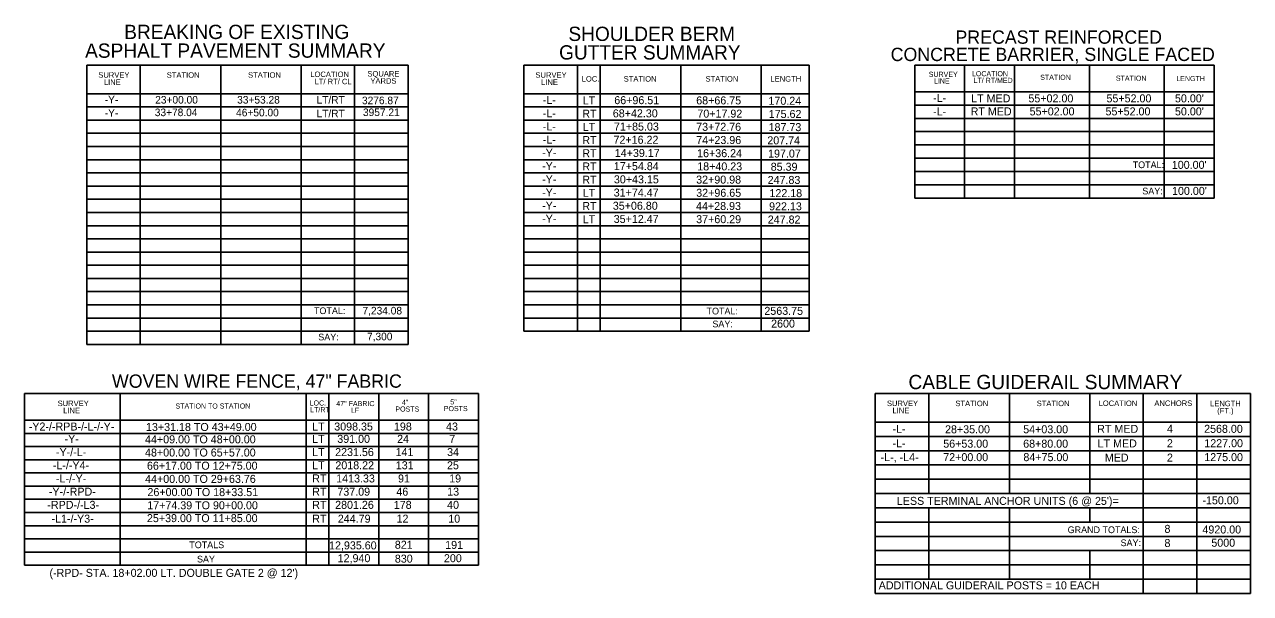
# Model space of a CAD drawing. Extents: x 573680 to 576464, y -53324 to -52224.
# Drawn here: x 575496 to 576464, y -53290 to -52840 of the extents above; entities that cross this region are included whole.
import ezdxf

# ---------------------------------------------------------------- set-up
doc = ezdxf.new("R2010")
doc.units = 0
for name, color, linetype in [('Old_Level_1', 7, 'Continuous'), ('Prop Dimension Text', 7, 'Continuous'), ('Sheet Summary Combination CELL', 7, 'Continuous'), ('Sheet Summary Combination Grid CELL', 7, 'Continuous')]:
    doc.layers.add(name, color=color, linetype=linetype)

msp = doc.modelspace()

# ---------------------------------------------------------------- linework, layer by layer
at = {"layer": 'Sheet Summary Combination CELL'}
for p, q in [((575672.56, -52872.26), (575672.56, -52872.26)), ((575678.2, -52872.35), (575678.2, -52872.35)), ((575686.37, -52872.17), (575686.37, -52872.17)), ((575691.42, -52872.26), (575691.42, -52872.26)), ((576017.76, -52872.26), (576017.76, -52872.26)), ((576023.4, -52872.35), (576023.4, -52872.35)), ((576031.57, -52872.17), (576031.57, -52872.17)), ((576036.62, -52872.26), (576036.62, -52872.26)), ((576317.64, -52872.25), (576317.64, -52872.25)), ((576322.89, -52872.34), (576322.89, -52872.34)), ((576330.49, -52872.17), (576330.49, -52872.17)), ((576335.2, -52872.25), (576335.2, -52872.25)), ((575697.34, -53131.65), (575697.34, -53131.65)), ((575702.59, -53131.73), (575702.59, -53131.73)), ((575710.2, -53131.56), (575710.2, -53131.56)), ((575714.9, -53131.65), (575714.9, -53131.65)), ((576295.3, -53131.65), (576295.3, -53131.65)), ((576300.94, -53131.74), (576300.94, -53131.74)), ((576309.1, -53131.56), (576309.1, -53131.56)), ((576314.16, -53131.65), (576314.16, -53131.65))]:
    msp.add_line(p, q, dxfattribs=at)
at = {"layer": 'Sheet Summary Combination Grid CELL'}
for p, q in [((575545.08, -52872.21), (575799, -52872.21)), ((575545.08, -52872.21), (575545.08, -53092.83)), ((575587.41, -52872.21), (575587.41, -53092.83)), ((575650.9, -52872.21), (575650.9, -53092.83)), ((575714.35, -52872.21), (575714.35, -53092.83)), ((575756.67, -52872.21), (575756.67, -53092.83)), ((575799, -52872.21), (575799, -53092.83)), ((575890.28, -52872.21), (576115.56, -52872.21)), ((575890.28, -52872.21), (575890.28, -53082.41)), ((575932.61, -52872.21), (575932.61, -53082.41)), ((575950.66, -52872.21), (575950.66, -53082.41)), ((576014.15, -52872.21), (576014.15, -53082.41)), ((576077.6, -52872.21), (576077.6, -53082.41)), ((576115.56, -52872.21), (576115.56, -53082.41)), ((576198.96, -52872.21), (576435.35, -52872.21)), ((576198.96, -52872.21), (576198.96, -52977.24)), ((576238.36, -52872.21), (576238.36, -52977.24)), ((576277.81, -52872.21), (576277.81, -52977.24)), ((576336.88, -52872.21), (576336.88, -52977.24)), ((576395.95, -52872.21), (576395.95, -52977.24)), ((576435.35, -52872.21), (576435.35, -52977.24)), ((575545.08, -52894.78), (575799, -52894.78)), ((575890.28, -52894.78), (576115.56, -52894.78)), ((576198.96, -52893.22), (576435.35, -52893.22)), ((575545.08, -52905.2), (575799, -52905.2)), ((575890.28, -52905.2), (576115.56, -52905.2)), ((576198.96, -52903.72), (576435.35, -52903.72)), ((575545.08, -52915.62), (575799, -52915.62)), ((575890.28, -52915.62), (576115.56, -52915.62)), ((576198.96, -52914.22), (576435.35, -52914.22)), ((576198.96, -52924.73), (576435.35, -52924.73)), ((575545.08, -52926.05), (575799, -52926.05)), ((575890.28, -52926.05), (576115.56, -52926.05)), ((576198.96, -52935.23), (576435.35, -52935.23)), ((575545.08, -52936.47), (575799, -52936.47)), ((575890.28, -52936.47), (576115.56, -52936.47)), ((575545.08, -52946.89), (575799, -52946.89)), ((575890.28, -52946.89), (576115.56, -52946.89)), ((576198.96, -52945.73), (576435.35, -52945.73)), ((576198.96, -52945.73), (576435.35, -52945.73)), ((576198.96, -52945.73), (576435.35, -52945.73)), ((575545.08, -52957.32), (575799, -52957.32)), ((575890.28, -52957.32), (576115.56, -52957.32)), ((576198.96, -52956.24), (576435.35, -52956.24)), ((575545.08, -52967.74), (575799, -52967.74)), ((575890.28, -52967.74), (576115.56, -52967.74)), ((576198.96, -52966.74), (576435.35, -52966.74)), ((575545.08, -52978.17), (575799, -52978.17)), ((575890.28, -52978.17), (576115.56, -52978.17)), ((576198.96, -52977.24), (576435.35, -52977.24)), ((575545.08, -52988.59), (575799, -52988.59)), ((575890.28, -52988.59), (576115.56, -52988.59)), ((575545.08, -52999.01), (575799, -52999.01)), ((575890.28, -52999.01), (576115.56, -52999.01)), ((575545.08, -53009.44), (575799, -53009.44)), ((575890.28, -53009.44), (576115.56, -53009.44)), ((575545.08, -53019.86), (575799, -53019.86)), ((575890.28, -53019.86), (576115.56, -53019.86)), ((575545.08, -53030.29), (575799, -53030.29)), ((575545.08, -53030.29), (575799, -53030.29)), ((575545.08, -53030.29), (575799, -53030.29)), ((575890.28, -53030.29), (576115.56, -53030.29)), ((575545.08, -53040.71), (575799, -53040.71)), ((575890.28, -53040.71), (576115.56, -53040.71)), ((575545.08, -53051.13), (575799, -53051.13)), ((575890.28, -53051.13), (576115.56, -53051.13)), ((575545.08, -53061.56), (575799, -53061.56)), ((575890.28, -53061.56), (576115.56, -53061.56)), ((575545.08, -53071.98), (575799, -53071.98)), ((575890.28, -53071.98), (576115.56, -53071.98)), ((575545.08, -53082.41), (575799, -53082.41)), ((575890.28, -53082.41), (576115.56, -53082.41)), ((575545.08, -53092.83), (575799, -53092.83)), ((575495.97, -53131.61), (575854.46, -53131.61)), ((575495.97, -53131.61), (575495.97, -53267.27)), ((575571.5, -53131.61), (575571.5, -53267.27)), ((575718.45, -53131.61), (575718.45, -53267.27)), ((575736.24, -53131.61), (575736.24, -53267.27)), ((575775.65, -53131.61), (575775.65, -53267.27)), ((575815.06, -53131.61), (575815.06, -53267.27)), ((575854.46, -53131.61), (575854.46, -53267.27)), ((576167.82, -53131.61), (576464.06, -53131.61)), ((576167.82, -53131.61), (576167.82, -53289.54)), ((576210.15, -53131.61), (576210.15, -53210.57)), ((576273.64, -53131.61), (576273.64, -53210.57)), ((576337.08, -53131.61), (576337.08, -53210.57)), ((576379.41, -53131.61), (576379.41, -53289.54)), ((576421.74, -53131.61), (576421.74, -53289.54)), ((576464.06, -53131.61), (576464.06, -53289.54)), ((575495.97, -53152.61), (575854.46, -53152.61)), ((576167.82, -53154.17), (576464.06, -53154.17)), ((575495.97, -53163.04), (575854.46, -53163.04)), ((576167.82, -53165.45), (576464.06, -53165.45)), ((575495.97, -53173.46), (575854.46, -53173.46)), ((576167.82, -53176.73), (576464.06, -53176.73)), ((575495.97, -53183.88), (575854.46, -53183.88)), ((575495.97, -53194.31), (575854.46, -53194.31)), ((576167.82, -53188.01), (576464.06, -53188.01)), ((575495.97, -53204.73), (575854.46, -53204.73)), ((576167.82, -53199.29), (576464.06, -53199.29)), ((575495.97, -53215.15), (575854.46, -53215.15)), ((576167.82, -53210.57), (576464.06, -53210.57)), ((576167.82, -53210.57), (576464.06, -53210.57)), ((575495.97, -53225.58), (575854.46, -53225.58)), ((575571.5, -53225.58), (575854.46, -53225.58)), ((575571.5, -53225.58), (575854.46, -53225.58)), ((576167.82, -53221.86), (576464.06, -53221.86)), ((576210.15, -53221.86), (576210.15, -53278.26)), ((576273.64, -53221.86), (576273.64, -53278.26)), ((576337.08, -53221.86), (576337.08, -53233.14)), ((576167.82, -53233.14), (576464.06, -53233.14)), ((575495.97, -53236.08), (575854.46, -53236.08)), ((575571.5, -53236), (575854.46, -53236)), ((575571.5, -53236), (575854.46, -53236)), ((576167.82, -53244.42), (576464.06, -53244.42)), ((575495.97, -53246.43), (575854.46, -53246.43)), ((575571.5, -53246.43), (575854.46, -53246.43)), ((575495.97, -53256.85), (575854.46, -53256.85)), ((575571.5, -53256.85), (575854.46, -53256.85)), ((576167.82, -53255.7), (576464.06, -53255.7)), ((576337.08, -53255.7), (576337.08, -53278.26)), ((575495.97, -53267.27), (575854.46, -53267.27)), ((575571.5, -53267.27), (575854.46, -53267.27)), ((576167.82, -53266.98), (576464.06, -53266.98)), ((576167.82, -53278.26), (576464.06, -53278.26)), ((576167.82, -53289.54), (576464.06, -53289.54))]:
    msp.add_line(p, q, dxfattribs=at)

# ---------------------------------------------------------------- texts
at = {"layer": 'Old_Level_1'}
for s, p in [('TOTALS', (575626.08, -53253.75)), ('SAY', (575632.17, -53265.04))]:
    msp.add_text(s, height=5.293, rotation=0.00004, dxfattribs=at).set_placement(p)
at = {"layer": 'Prop Dimension Text'}
for s, height, p in [('-Y-', 6, (575559.33, -52902.39)), ('23+00.00', 6, (575599.17, -52902.55)), ('33+53.28', 6, (575663.88, -52902.55)), ('LT/RT', 6, (575726.58, -52902.58)), ('-L-', 6.317, (576213.42, -52901.25)), ('LT MED', 6.317, (576243.49, -52901.6)), ('55+02.00', 6.317, (576288.71, -52901.6)), ('55+52.00', 6.317, (576350.34, -52901.6)), ("50.00'", 6.317, (576404.44, -52901.6)), ('3276.87', 6, (575762.45, -52903.06)), ('-L-', 6.317, (575905.19, -52902.89)), ('LT', 6.317, (575936.8, -52903.26)), ('66+96.51', 6.317, (575961.68, -52903.03)), ('68+66.75', 6.317, (576026.39, -52903.22)), ('170.24', 6.317, (576083.43, -52903.49)), ('-L-', 6.317, (576213.42, -52911.89)), ('RT MED', 6.317, (576243.11, -52911.89)), ('55+02.00', 6.317, (576289.65, -52911.89)), ('55+52.00', 6.317, (576349.58, -52911.89)), ("50.00'", 6.317, (576404.44, -52911.89)), ('-Y-', 6, (575559.33, -52913)), ('33+78.04', 6, (575598.83, -52912.49)), ('46+50.00', 6, (575663.05, -52912.63)), ('LT/RT', 6, (575726.58, -52913.4)), ('3957.21', 6, (575763.24, -52912.41)), ('-L-', 6.317, (575905.19, -52913.32)), ('RT', 6.317, (575936.43, -52913.68)), ('68+42.30', 6.317, (575960.52, -52913.45)), ('70+17.92', 6.317, (576027.29, -52913.65)), ('175.62', 6.317, (576083.64, -52913.92)), ('-L-', 6.317, (575905.19, -52923.74)), ('LT', 6.317, (575936.8, -52924.1)), ('71+85.03', 6.317, (575961.41, -52923.87)), ('73+72.76', 6.317, (576026.35, -52924.07)), ('187.73', 6.317, (576083.53, -52924.34)), ('-L-', 6.317, (575905.19, -52934.17)), ('RT', 6.317, (575936.43, -52934.53)), ('72+16.22', 6.317, (575961.08, -52934.3)), ('74+23.96', 6.317, (576026.43, -52934.5)), ('207.74', 6.317, (576082.54, -52934.76)), ('-Y-', 6.317, (575904.69, -52944.59)), ('RT', 6.317, (575936.43, -52944.95)), ('14+39.17', 6.317, (575962.08, -52944.72)), ('16+36.24', 6.317, (576027.09, -52944.92)), ('197.07', 6.317, (576083.13, -52945.19)), ('-Y-', 6.317, (575904.69, -52955.01)), ('RT', 6.317, (575936.43, -52955.38)), ('17+54.84', 6.317, (575961.31, -52955.15)), ('18+40.23', 6.317, (576027.19, -52955.34)), ('85.39', 6.317, (576085.21, -52955.61)), ("100.00'", 6.317, (576401.94, -52954.12)), ('-Y-', 6.317, (575904.69, -52965.44)), ('RT', 6.317, (575936.43, -52965.8)), ('30+43.15', 6.317, (575961.37, -52965.57)), ('32+90.98', 6.317, (576026.34, -52965.77)), ('247.83', 6.317, (576082.78, -52966.03)), ('-Y-', 6.317, (575904.69, -52975.86)), ('LT', 6.317, (575936.8, -52976.22)), ('31+74.47', 6.317, (575961.24, -52975.99)), ('32+96.65', 6.317, (576026.39, -52976.19)), ('122.18', 6.317, (576084.2, -52976.46)), ("100.00'", 6.317, (576402.11, -52974.7)), ('-Y-', 6.317, (575904.69, -52986.29)), ('RT', 6.317, (575936.43, -52986.65)), ('35+06.80', 6.317, (575960.52, -52986.42)), ('44+28.93', 6.317, (576026.26, -52986.62)), ('922.13', 6.317, (576083.93, -52986.88)), ('-Y-', 6.317, (575904.69, -52996.71)), ('LT', 6.317, (575936.8, -52997.07)), ('35+12.47', 6.317, (575961.24, -52996.84)), ('37+60.29', 6.317, (576026.37, -52997.04)), ('247.82', 6.317, (576082.88, -52997.31)), ('7,234.08', 6, (575762.84, -53069.15)), ('2563.75', 6.317, (576080.2, -53069.45)), ('2600', 6.317, (576085.54, -53079.5)), ('7,300', 6, (575766.43, -53089.54)), ('-Y2-/-RPB-/-L-/-Y-', 6.3175, (575499.31, -53160.82)), ('13+31.18 TO 43+49.00', 6.3175, (575591.89, -53161.17)), ('LT', 6.317, (575723.16, -53160.82)), ('3098.35', 6.317, (575740.54, -53160.82)), ('198', 6.317, (575787.68, -53160.82)), ('43', 6.317, (575828.84, -53160.82)), ('-L-', 6.317, (576181.37, -53162.64)), ('28+35.00', 6.317, (576222.87, -53163)), ('54+03.00', 6.317, (576284.58, -53163)), ('RT MED', 6.317, (576343.02, -53162.64)), ('4', 6.32, (576398.09, -53162.64)), ('2568.00', 6.317, (576427.45, -53162.64)), ('-Y-', 6.317, (575527.58, -53170.57)), ('44+09.00 TO 48+00.00', 6.3175, (575591.14, -53170.92)), ('LT', 6.317, (575723.16, -53170.57)), ('391.00', 6.317, (575742.94, -53170.57)), ('24', 6.317, (575790.23, -53170.57)), ('7', 6.32, (575831.38, -53170.57)), ('-Y-/-L-', 6.317, (575520.81, -53180.99)), ('48+00.00 TO 65+57.00', 6.3175, (575591.14, -53181.34)), ('LT', 6.317, (575723.16, -53180.99)), ('2231.56', 6.317, (575741.26, -53180.99)), ('141', 6.317, (575788.98, -53180.99)), ('34', 6.317, (575829.66, -53180.99)), ('-L-', 6.317, (576181.37, -53174)), ('56+53.00', 6.317, (576221.45, -53174.35)), ('68+80.00', 6.317, (576284.58, -53174.35)), ('LT MED', 6.317, (576343.35, -53174.17)), ('2', 6.32, (576398.09, -53174)), ('1227.00', 6.317, (576427.6, -53174)), ('-L-/-Y4-', 6.317, (575518.31, -53191.41)), ('66+17.00 TO 12+75.00', 6.3175, (575592.65, -53191.77)), ('LT', 6.317, (575723.16, -53191.41)), ('2018.22', 6.317, (575741.44, -53191.41)), ('131', 6.317, (575789.15, -53191.41)), ('25', 6.317, (575829.6, -53191.41)), ('-L-, -L4-', 6.317, (576172, -53185)), ('72+00.00', 6.317, (576221.45, -53185)), ('84+75.00', 6.317, (576284.75, -53185)), ('MED', 6.317, (576349.04, -53185.37)), ('2', 6.32, (576398.09, -53185.35)), ('1275.00', 6.317, (576427.58, -53185)), ('-L-/-Y-', 6.317, (575520.81, -53201.83)), ('44+00.00 TO 29+63.76', 6.3175, (575591.2, -53202.19)), ('RT', 6.317, (575723.16, -53201.83)), ('1413.33', 6.317, (575742.09, -53201.83)), ('91', 6.317, (575790.91, -53201.83)), ('19', 6.317, (575831.31, -53201.83)), ('-Y-/-RPD-', 6.317, (575515.18, -53212.26)), ('26+00.00 TO 18+33.51', 6.3175, (575593.05, -53212.61)), ('RT', 6.317, (575723.16, -53212.26)), ('737.09', 6.317, (575743.02, -53212.26)), ('46', 6.317, (575789.6, -53212.26)), ('13', 6.317, (575829.74, -53212.26)), ("LESS TERMINAL ANCHOR UNITS (6 @ 25')=", 6.3175, (576184.83, -53219.55)), ('-150.00', 6.317, (576426.13, -53219.09)), ('-RPD-/-L3-', 6.317, (575514, -53222.68)), ('17+74.39 TO 90+00.00', 6.3175, (575592.89, -53223.03)), ('RT', 6.317, (575723.16, -53222.68)), ('2801.26', 6.317, (575741.26, -53222.68)), ('178', 6.317, (575787.56, -53222.68)), ('40', 6.317, (575829.68, -53222.68)), ('-L1-/-Y3-', 6.317, (575517.3, -53233.6)), ('25+39.00 TO 11+85.00', 6.3175, (575592.65, -53233.18)), ('RT', 6.317, (575723.16, -53233.6)), ('244.79', 6.317, (575743.38, -53233.6)), ('12', 6.317, (575789.75, -53233.6)), ('10', 6.317, (575830.61, -53233.6)), ('8', 6.32, (576396.15, -53241.66)), ('4920.00', 6.317, (576426.13, -53242.15)), ('8', 6.32, (576396.15, -53252.83)), ('5000', 6.317, (576433.16, -53252.61)), ("(-RPD- STA. 18+02.00 LT. DOUBLE GATE 2 @ 12')", 6.3175, (575515.68, -53276.4)), ('ADDITIONAL GUIDERAIL POSTS = 10 EACH', 6.3175, (576170.5, -53286.28))]:
    msp.add_text(s, height=height, dxfattribs=at).set_placement(p)
for s, p in [('12,935.60', (575736.46, -53254.71)), ('821', (575788.39, -53254.21)), ('191', (575828.16, -53254.33)), ('12,940', (575743.25, -53264.81)), ('830', (575788.4, -53265.17)), ('200', (575827.17, -53264.84))]:
    msp.add_text(s, height=6.317, rotation=0.00004, dxfattribs=at).set_placement(p)
at = {"layer": 'Sheet Summary Combination CELL'}
for s, height, p in [('BREAKING OF EXISTING', 11.2813, (575574.71, -52851.59)), ('SHOULDER BERM', 11.2813, (575925.45, -52853.11)), ('PRECAST REINFORCED', 10.5029, (576231.06, -52855.32)), ('ASPHALT PAVEMENT SUMMARY', 11.2813, (575543.79, -52866.39)), ('GUTTER SUMMARY', 11.2813, (575918.08, -52867.77)), ('CONCRETE BARRIER, SINGLE FACED', 10.5029, (576179.92, -52868.98)), ('WOVEN WIRE FENCE, 47" FABRIC', 10.5029, (575565, -53127.05)), ('CABLE GUIDERAIL SUMMARY', 11.2813, (576193.98, -53128.15))]:
    msp.add_text(s, height=height, rotation=0.01193, dxfattribs=at).set_placement(p)
for s, height, p in [('LOCATION', 4.033, (576244.13, -52880.95)), ('SURVEY', 4.332, (575554.24, -52882.13)), ('LINE', 4.332, (575558.67, -52887.81)), ('STATION', 4.332, (575608.3, -52882.18)), ('STATION', 4.332, (575672.5, -52882.16)), ('LOCATION', 4.332, (575721.61, -52881.6)), ('LT/ RT/ CL', 4.332, (575725.03, -52887.29)), ('SURVEY', 4.332, (575899.44, -52882.13)), ('LINE', 4.332, (575903.87, -52887.81)), ('LOC.', 4.332, (575935.98, -52885.21)), ('STATION', 4.332, (575969.12, -52885.21)), ('STATION', 4.332, (576033.74, -52885.2)), ('LENGTH', 4.332, (576084.99, -52885.2)), ('SURVEY', 4.033, (576209.99, -52881.44)), ('LINE', 4.033, (576214.11, -52886.74)), ('LT/ RT/MED', 4.033, (576245.35, -52886.25)), ('STATION', 4.033, (576298.01, -52883.82)), ('STATION', 4.033, (576357.78, -52884.53)), ('TOTAL:', 5.293, (576371.05, -52953.55)), ('SAY:', 5.293, (576378.64, -52974.31)), ('TOTAL:', 5.293, (575724.54, -53068.84)), ('TOTAL:', 5.293, (576034.55, -53069.11)), ('SAY:', 5.293, (576039.16, -53079.29)), ('SAY:', 5.293, (575727.94, -53089.61)), ('SURVEY', 4.332, (575522.09, -53141.52)), ('LOC.', 4.033, (575721.12, -53141.08)), ('47" FABRIC', 4.033, (575742.17, -53141.53)), ('4"', 4.033, (575793.98, -53140.58)), ('5"', 4.033, (575832.19, -53140.2)), ('SURVEY', 4.332, (576176.98, -53141.52)), ('STATION', 4.332, (576231.04, -53141.57)), ('STATION', 4.332, (576295.24, -53141.55)), ('LOCATION', 4.332, (576344.12, -53141.46)), ('ANCHORS', 4.332, (576388.16, -53141.41)), ('LENGTH', 4.332, (576432.14, -53141.64)), ('LINE', 4.332, (575526.51, -53147.21)), ('STATION TO STATION', 4.0331, (575615.19, -53143.5)), ('LT/RT', 4.033, (575721.49, -53146.37)), ('LF', 4.033, (575753.73, -53146.83)), ('POSTS', 4.033, (575788.82, -53145.87)), ('POSTS', 4.033, (575827.03, -53145.49)), ('LINE', 4.332, (576181.4, -53147.21)), ('(FT.)', 4.332, (576437.77, -53147.33)), ('GRAND TOTALS:', 5.2929, (576319.7, -53241.86)), ('SAY:', 5.293, (576361.47, -53252.15))]:
    msp.add_text(s, height=height, dxfattribs=at).set_placement(p)
at = {"layer": 'Sheet Summary Combination Grid CELL'}
for s, height, p in [('SQUARE', 4.332, (575766.71, -52881.18)), ('YARDS', 4.332, (575769.11, -52886.86)), ('LENGTH', 4.033, (576405.5, -52884.79))]:
    msp.add_text(s, height=height, dxfattribs=at).set_placement(p)

doc.saveas('drawing.dxf')
